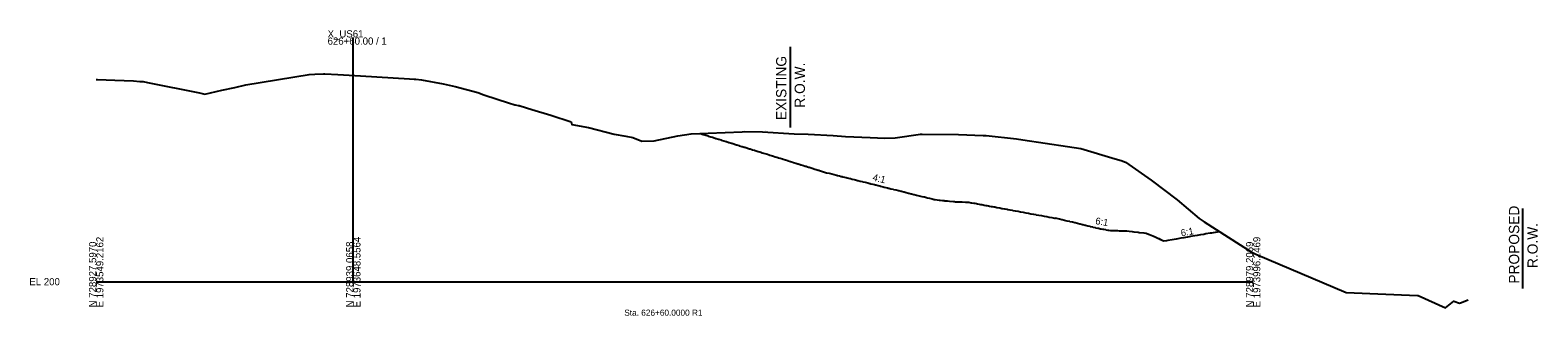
# Model space of a CAD drawing. Extents: x -26 to 630, y -39 to 9098.
# Drawn here: x -26 to 561, y 6487 to 6598 of the extents above; entities that cross this region are included whole.
import ezdxf

# ---------------------------------------------------------------- set-up
doc = ezdxf.new("R2010")
doc.units = 0
for name, color, linetype in [('CONST_DCH', 7, 'Continuous'), ('Default', 7, 'Continuous'), ('Draft_XS_Grid', 7, 'Continuous'), ('Draft_XS_Text', 7, 'Continuous'), ('DTM_X_GROUND', 7, 'Continuous'), ('X_DTM_CONTOURS_MAJOR', 7, 'Continuous'), ('XS_CELL', 7, 'Continuous'), ('XS_P_GROUND', 7, 'Continuous'), ('XS_P_ROW', 7, 'Continuous'), ('XS_P_TX_FS_BS', 7, 'Continuous'), ('XS_X_ROW', 7, 'Continuous')]:
    doc.layers.add(name, color=color, linetype=linetype)

msp = doc.modelspace()

# ---------------------------------------------------------------- linework, layer by layer
at = {"layer": 'DTM_X_GROUND'}
msp.add_lwpolyline([(0, 6578.62), (0.55, 6578.62), (7.24, 6578.4), (14.54, 6578.16), (17.02, 6577.93), (18.26, 6577.81), (19.93, 6577.52), (40.15, 6573.42), (42.29, 6572.96), (48.82, 6574.44), (53.88, 6575.59), (58.21, 6576.6), (82.77, 6580.58), (85.1, 6580.78), (88.46, 6580.86), (88.95, 6580.88), (93.93, 6580.61), (102.76, 6580.13), (121.82, 6578.92), (123.62, 6578.81), (124.29, 6578.72), (126.46, 6578.46), (134.99, 6576.9), (139.56, 6575.95), (144.09, 6574.72), (148.44, 6573.53), (150.83, 6572.74), (160.75, 6569.47), (162.43, 6568.91), (162.86, 6568.77), (162.95, 6568.76), (164.13, 6568.55), (164.56, 6568.47), (164.73, 6568.44), (164.87, 6568.42), (164.96, 6568.4), (169.41, 6567.01), (176.84, 6564.77), (184.74, 6562.22), (184.97, 6561.08), (191.48, 6559.92), (201.51, 6557.42), (206, 6556.62), (208.73, 6556.15), (212.28, 6554.67), (217.02, 6554.8), (226.29, 6556.74), (231.37, 6557.57), (251.23, 6558.28), (252.32, 6558.39), (259.13, 6558.26), (271.42, 6557.54), (276.89, 6557.41), (286.64, 6556.83), (291.43, 6556.46), (301.01, 6556.05), (306.77, 6555.87), (310.77, 6555.95), (320.63, 6557.35), (320.8, 6557.35), (321.24, 6557.4), (335.44, 6557.31), (344.94, 6556.92), (345.59, 6556.9), (346.21, 6556.89), (357.9, 6555.6), (360.45, 6555.13), (377.79, 6552.6), (383, 6551.76), (396.32, 6547.8), (398.61, 6547.16), (400.38, 6546.5), (410.3, 6539.48), (420.46, 6531.81), (429.02, 6524.64), (430.91, 6523.31), (449.68, 6511.41), (449.98, 6511.21), (451.03, 6510.69), (486.18, 6495.86), (513.91, 6494.58), (514.15, 6494.59), (524.77, 6489.77), (528.11, 6492.38), (530.2, 6491.64), (530.24, 6491.66), (530.25, 6491.66), (530.25, 6491.66), (530.71, 6491.84), (533.62, 6492.98)], dxfattribs=at)
at = {"layer": 'XS_CELL'}
for p, q in [((100, 6500), (100, 6595)), ((0, 6500), (100, 6500)), ((100, 6500), (450, 6500))]:
    msp.add_line(p, q, dxfattribs=at)
at = {"layer": 'XS_P_GROUND'}
for points in [[(234.82, 6557.7), (235.06, 6557.62), (235.06, 6557.62), (236.06, 6557.31), (236.08, 6557.31), (237.06, 6557), (237.1, 6556.99), (238.06, 6556.69), (238.12, 6556.67), (239.06, 6556.38), (239.11, 6556.37), (239.67, 6556.19), (239.7, 6556.18), (240.06, 6556.07), (240.15, 6556.04), (241.06, 6555.76), (241.16, 6555.73), (242.06, 6555.45), (242.16, 6555.42), (243.06, 6555.14), (243.17, 6555.1), (244.07, 6554.83), (244.18, 6554.79), (245.07, 6554.52), (245.18, 6554.48), (246.07, 6554.2), (246.19, 6554.17), (247.07, 6553.89), (247.2, 6553.85), (248.07, 6553.58), (248.21, 6553.54), (249.07, 6553.27), (249.22, 6553.22), (250.07, 6552.96), (250.23, 6552.91), (251.07, 6552.65), (251.25, 6552.6), (252.07, 6552.34), (252.26, 6552.28), (253.07, 6552.03), (253.28, 6551.96), (254.07, 6551.72), (254.31, 6551.65), (255.07, 6551.41), (255.33, 6551.33), (256.07, 6551.1), (256.37, 6551.01), (257.07, 6550.79), (257.41, 6550.68), (258.07, 6550.48), (258.46, 6550.35), (259.07, 6550.17), (259.54, 6550.02), (260.07, 6549.85), (260.64, 6549.68), (261.07, 6549.54), (261.8, 6549.32), (262.07, 6549.23), (263.07, 6548.92), (263.07, 6548.92), (263.08, 6548.92), (263.08, 6548.92), (263.47, 6548.8), (264.08, 6548.61), (264.76, 6548.4), (265.08, 6548.3), (265.36, 6548.21), (266.08, 6547.99), (266.89, 6547.74), (267.08, 6547.68), (267.25, 6547.63), (268.08, 6547.37), (269.01, 6547.08), (269.08, 6547.06), (269.14, 6547.04), (270.08, 6546.75), (271.02, 6546.45), (271.08, 6546.44), (271.14, 6546.42), (272.08, 6546.13), (272.91, 6545.87), (273.08, 6545.81), (273.85, 6545.58), (274.08, 6545.5), (274.21, 6545.46), (275.08, 6545.19), (275.77, 6544.98), (276.08, 6544.88), (276.67, 6544.7), (277.08, 6544.57), (277.31, 6544.5), (278.08, 6544.26), (278.87, 6544.02), (279.08, 6543.95), (279.49, 6543.83), (280.08, 6543.64), (280.77, 6543.43), (281.08, 6543.33), (281.36, 6543.24), (282.08, 6543.02), (282.92, 6542.76), (283.09, 6542.71), (283.23, 6542.66), (284.09, 6542.4), (284.17, 6542.38), (285.09, 6542.15), (285.6, 6542.02), (286.09, 6541.9), (286.97, 6541.68), (287.09, 6541.65), (287.91, 6541.45), (288.09, 6541.4), (288.3, 6541.35), (289.09, 6541.15), (289.77, 6540.98), (290.09, 6540.9), (290.46, 6540.81), (291.09, 6540.66), (291.64, 6540.52), (292.09, 6540.41), (292.57, 6540.29), (293.09, 6540.16), (293.39, 6540.08), (294.09, 6539.91), (294.94, 6539.7), (295.09, 6539.66), (295.36, 6539.59), (296.09, 6539.41), (296.29, 6539.36), (297.09, 6539.16), (298.03, 6538.93), (298.09, 6538.91), (298.15, 6538.9), (299.09, 6538.67), (299.63, 6538.53), (300.09, 6538.42), (300.93, 6538.21), (301.09, 6538.17), (301.29, 6538.12), (302.1, 6537.92), (302.78, 6537.75), (303.1, 6537.67), (303.27, 6537.63), (304.1, 6537.42), (304.84, 6537.24), (305.1, 6537.17), (305.56, 6537.06), (306.1, 6536.92), (306.48, 6536.83), (307.1, 6536.68), (307.83, 6536.49), (308.1, 6536.43), (308.33, 6536.37), (309.1, 6536.18), (309.11, 6536.17), (310.1, 6535.93), (310.14, 6535.92), (311.1, 6535.68), (311.16, 6535.67), (312.1, 6535.43), (312.17, 6535.41), (313.1, 6535.18), (313.19, 6535.16), (314.1, 6534.94), (314.21, 6534.91), (315.1, 6534.69), (315.99, 6534.47), (316.1, 6534.44), (316.99, 6534.22), (317.1, 6534.19), (318.01, 6533.96), (318.1, 6533.94), (319.03, 6533.71), (319.1, 6533.69), (320.06, 6533.45), (320.1, 6533.44), (321.08, 6533.2), (321.1, 6533.19), (321.95, 6532.98), (322.11, 6532.95), (322.94, 6532.74), (323.11, 6532.7), (323.19, 6532.68), (324.11, 6532.45), (324.69, 6532.3), (325.11, 6532.2), (325.92, 6532), (326.11, 6531.95), (326.3, 6531.93), (327.11, 6531.84), (327.9, 6531.75), (328.11, 6531.72), (328.32, 6531.7), (329.11, 6531.61), (329.88, 6531.52), (330.11, 6531.5), (330.18, 6531.49), (330.33, 6531.47), (330.87, 6531.42), (331.07, 6531.4), (331.86, 6531.33), (333.49, 6531.18), (333.84, 6531.14), (334.2, 6531.11), (336.8, 6531.02), (338.09, 6530.97), (338.78, 6530.94), (339.12, 6530.93), (339.2, 6530.93), (339.36, 6530.92), (339.39, 6530.92), (340.37, 6530.73), (340.58, 6530.7), (341.38, 6530.55), (341.72, 6530.49), (342.39, 6530.36), (342.83, 6530.28), (343.4, 6530.17), (343.92, 6530.08), (344.42, 6529.99), (344.99, 6529.88), (345.43, 6529.8), (346.06, 6529.69), (346.44, 6529.62), (347.11, 6529.49), (347.45, 6529.43), (348.16, 6529.3), (348.46, 6529.24), (349.2, 6529.1), (349.47, 6529.06), (350.24, 6528.91), (350.49, 6528.87), (351.28, 6528.72), (351.5, 6528.68), (352.31, 6528.53), (352.51, 6528.5), (353.35, 6528.34), (353.52, 6528.31), (354.38, 6528.15), (354.53, 6528.12), (355.4, 6527.96), (355.55, 6527.94), (356.43, 6527.77), (356.56, 6527.75), (357.45, 6527.58), (357.57, 6527.56), (358.48, 6527.39), (358.58, 6527.38), (359.5, 6527.21), (359.59, 6527.19), (360.52, 6527.02), (360.6, 6527), (361.54, 6526.83), (361.62, 6526.82), (362.56, 6526.64), (362.63, 6526.63), (363.58, 6526.45), (363.64, 6526.44), (364.6, 6526.26), (364.65, 6526.26), (365.62, 6526.08), (365.66, 6526.07), (366.64, 6525.89), (366.68, 6525.88), (367.66, 6525.7), (367.69, 6525.7), (368.68, 6525.51), (368.7, 6525.51), (369.69, 6525.33), (369.71, 6525.32), (370.71, 6525.14), (370.72, 6525.14), (371.73, 6524.95), (371.73, 6524.95), (372.74, 6524.76), (372.75, 6524.76), (373.11, 6524.69)], [(408.39, 6518.77), (407.57, 6518.86), (407.46, 6518.87), (405.64, 6519.07), (405.26, 6519.11), (403.71, 6519.28), (403.06, 6519.35), (401.78, 6519.49), (400.86, 6519.59), (400.81, 6519.59), (400.76, 6519.6), (399.58, 6519.65), (398.68, 6519.69), (397.98, 6519.71), (397.4, 6519.74), (396.9, 6519.75), (396.47, 6519.76), (396.08, 6519.77), (395.73, 6519.78), (395.41, 6519.79), (395.1, 6519.79), (394.62, 6519.83), (393.88, 6519.94), (393.66, 6519.97), (392.87, 6520.09), (392.66, 6520.12), (391.86, 6520.24), (391.66, 6520.26), (390.89, 6520.38), (390.88, 6520.38), (390.85, 6520.39), (390.66, 6520.44), (389.84, 6520.63), (389.65, 6520.68), (388.82, 6520.88), (388.65, 6520.92), (387.81, 6521.13), (387.65, 6521.16), (386.8, 6521.37), (386.65, 6521.41), (385.79, 6521.62), (385.65, 6521.65), (384.78, 6521.86), (384.65, 6521.89), (383.77, 6522.11), (383.65, 6522.14), (382.75, 6522.35), (382.65, 6522.38), (381.74, 6522.6), (381.65, 6522.62), (380.73, 6522.85), (380.65, 6522.87), (379.72, 6523.09), (379.65, 6523.11), (378.71, 6523.34), (378.65, 6523.35), (377.69, 6523.58), (377.64, 6523.59), (376.68, 6523.83), (376.64, 6523.84), (375.67, 6524.07), (375.64, 6524.08), (374.66, 6524.32), (374.64, 6524.32), (373.65, 6524.57), (373.64, 6524.57), (373.11, 6524.69)], [(415.13, 6515.71), (414.32, 6516.14), (414.06, 6516.29), (413.44, 6516.62), (413.23, 6516.73), (412.41, 6517.08), (411.86, 6517.31), (411, 6517.67), (409.66, 6518.24), (409.35, 6518.37), (408.39, 6518.77)], [(436.96, 6519.47), (436.06, 6519.32), (435.91, 6519.29), (433.86, 6518.94), (433.34, 6518.85), (431.66, 6518.56), (430.76, 6518.4), (429.46, 6518.18), (428.19, 6517.96), (427.26, 6517.8), (425.61, 6517.52), (425.06, 6517.42), (423.03, 6517.07), (422.86, 6517.04), (421.87, 6516.87), (420.66, 6516.66), (420.07, 6516.56), (418.46, 6516.28), (416.8, 6516), (416.26, 6515.9), (415.13, 6515.71)]]:
    msp.add_lwpolyline(points, dxfattribs=at)
at = {"layer": 'XS_P_ROW'}
msp.add_line((554.73, 6528.41), (554.73, 6497.4), dxfattribs=at)
at = {"layer": 'XS_X_ROW'}
msp.add_line((270, 6560), (270, 6591.36), dxfattribs=at)

# ---------------------------------------------------------------- texts
at = {"layer": 'CONST_DCH'}
for p in [(415.13, 6515.71), (421.87, 6516.87)]:
    msp.add_text('X', height=0.001, dxfattribs=at).set_placement(p)
at = {"layer": 'Default'}
for height, p in [(0.12, (242.65, 6557.92)), (0.001, (408.39, 6518.77)), (0.001, (415.13, 6515.71))]:
    msp.add_text('X', height=height, dxfattribs=at).set_placement(p)
at = {"layer": 'Draft_XS_Grid'}
msp.add_text('-', height=0.0001, dxfattribs=at).set_placement((0, 6500))
at = {"layer": 'Draft_XS_Text'}
msp.add_text('Sta. 626+60.0000 R1', height=2.4, dxfattribs=at).set_placement((205.4, 6486.75))
at = {"layer": 'X_DTM_CONTOURS_MAJOR'}
msp.add_text('X', height=0.12, dxfattribs=at).set_placement((260.12, 6558.58))
at = {"layer": 'XS_CELL'}
for s, p in [('X_US61', (90, 6595)), ('626+60.00 / 1', (90, 6592.2)), ('EL 200', (-26, 6498.6))]:
    msp.add_text(s, height=2.8, dxfattribs=at).set_placement(p)
for s, p in [('N 728927.5970', (0, 6490)), ('E 1973549.2162', (2.8, 6490)), ('N 728939.0658', (100, 6490)), ('E 1973648.5564', (102.8, 6490)), ('N 728979.2069', (450, 6490)), ('E 1973996.2469', (452.8, 6490))]:
    msp.add_text(s, height=2.8, rotation=90, dxfattribs=at).set_placement(p)
at = {"layer": 'XS_P_ROW'}
for s, p in [('EXISTING', (268.46, 6562.84)), ('R.O.W.', (275.66, 6567.69)), ('PROPOSED', (553.48, 6499.25)), ('R.O.W.', (560.68, 6505.32))]:
    msp.add_text(s, height=4, rotation=90, dxfattribs=at).set_placement(p)
at = {"layer": 'XS_P_TX_FS_BS'}
for s, rotation, p in [('4:1', 346.57811, (301.8, 6539.41)), ('6:1', 350.46289, (388.48, 6522.42)), ('6:1', 9.79046, (422.09, 6517.6))]:
    msp.add_text(s, height=2.7, rotation=rotation, dxfattribs=at).set_placement(p)

doc.saveas('drawing.dxf')
